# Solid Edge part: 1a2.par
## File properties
Author: edge
Template: jis part.par
Last saved by: edge
Revision: 15
Application: Solid Edge
Density: 7833.000 kg/m^3
Accuracy: 0.990
文書内容のタイプ: 0
Material: 鋼鉄
面のスタイル: Steel
塗りつぶしのスタイル: ANSI32(Steel)
バーチャルスタイル: 鋼鉄 機械仕上げ
Coef. of Thermal Exp: 0.0
Thermal Conductivity: 32.0
Specific Heat: 481.0
Modulus of Elasticity: 199947953000.0
Poisson's Ratio: 0.29
Yield Stress: 262000766.0
Ultimate Stress: 358527364.0
Elongation: 0.0
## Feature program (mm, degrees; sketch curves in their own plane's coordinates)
sketch for "unnamed Protrusion 1" plane through (0, 0, 0) normal (0, 0, 1) x-axis (1, 0, 0)
  line (-75, 60) -> (75, 60)
  line (75, 60) -> (75, -60)
  line (75, -60) -> (-75, -60)
  line (-75, -60) -> (-75, 60)
  dimension (linear) = 75
  dimension (linear) = 75
extrude "unnamed Protrusion 1" add finite 50 symmetric
sketch for "unnamed Cutout 1" plane through (0, 0, 0) normal (0, 0, 1) x-axis (1, 0, 0)
  circle centre (0, 0) radius 20
extrude "unnamed Cutout 1" cut through
sketch for "ExtrudedCutout_2" plane through (0, 0, 15) normal (0, 0, 1) x-axis (1, 0, 0)
  circle centre (0, 0) radius 27.5
extrude "ExtrudedCutout_2" cut through along +normal  Profile_Plane1_Distance = 15 mm
sketch for "切り抜き_3_Profile_Plane1" plane through (0, 0, 2) normal (0, 0, 1) x-axis (1, 0, 0)
  circle centre (0, 0) radius 27.5
extrude "切り抜き_3_Profile_Plane1" cut through along -normal  Distance = 2 mm
sketch for "unnamed Cutout 2" #1 plane through (0, 0, 0) normal (0, 0, 1) x-axis (1, 0, 0)
  circle centre (-50, 0) radius 6
sketch for "unnamed Cutout 2" #2 plane through (0, 0, 0) normal (0, 0, 1) x-axis (1, 0, 0)
  circle centre (50, 0) radius 6
extrude "unnamed Cutout 2" cut through along +normal
sketch for "unnamed Cutout 3" plane through (0, 0, 0) normal (0, 0, 1) x-axis (1, 0, 0)
  line (70, 0) -> (0, 55)
  line (0, 55) -> (-70, 0)
  line (-70, 0) -> (0, -55)
  line (0, -55) -> (70, 0)
extrude "unnamed Cutout 3" cut through along +normal
fillet "Round_1" radius 40
fillet "Round_2" radius 40
fillet "Round_3" radius 10
fillet "Round_4" radius 10
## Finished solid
Body 1: solid body, 17 faces, 34 edges, 16 vertices.
  Faces by surface: cylinder 9, plane 8
  Edges by curve: circle 18, line 16
Bounding box of the edges (mm): 127.628 x 88.260 x 50.000, from (-63.8141, -44.13, -25) to (63.8141, 44.13, 25).
Cylindrical faces by radius (mm): R6 x2, R10 x2, R20 x1, R27.5 x2, R40 x2
Planar faces by outward normal: +z 2, -z 2, oblique 4
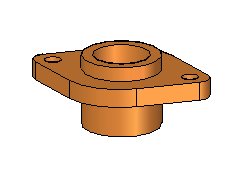
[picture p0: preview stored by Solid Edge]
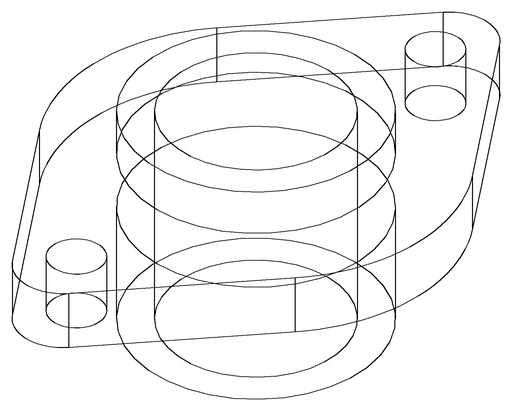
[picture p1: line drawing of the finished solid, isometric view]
